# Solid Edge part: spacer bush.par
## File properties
Author: Deepak Maini
Template: Normal.par
Last saved by: Robert a Rhodes jr
Revision: 4
Application: Solid Edge
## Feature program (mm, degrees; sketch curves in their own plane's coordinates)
sketch for "unnamed Protrusion 1" plane through (0, 0, 0) normal (0, 0, 1) x-axis (1, 0, 0)
  circle centre (0, 0) radius 13
extrude "unnamed Protrusion 1" add finite 24 along +normal
sketch for "unnamed Hole 1" plane through (0, 0, 24) normal (0, 0, 1) x-axis (0, 1, 0)
hole "unnamed Hole 1" through
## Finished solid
Body 1: solid body, 4 faces, 4 edges, 0 vertices.
  Faces by surface: plane 2, cone 1, cylinder 1
  Edges by curve: circle 4
Bounding box of the edges (mm): 26.000 x 26.000 x 24.000, from (-13, -13, 0) to (13, 13, 24).
Cylindrical faces by radius (mm): R8 x1
Conical faces (half-angle, radius in mm at the cone's reference point): 2 deg R13 x1
Planar faces by outward normal: +z 1, -z 1
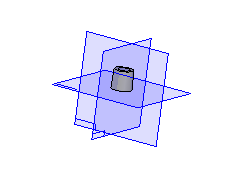
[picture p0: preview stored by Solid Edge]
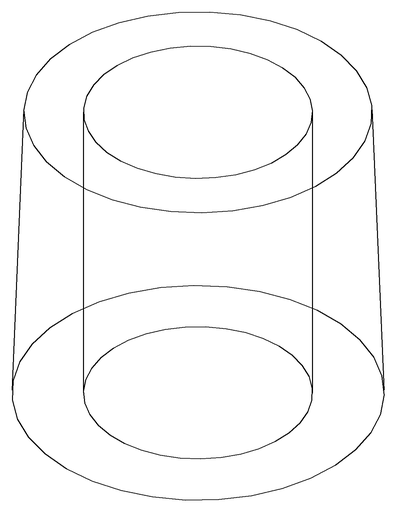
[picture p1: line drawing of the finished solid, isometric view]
